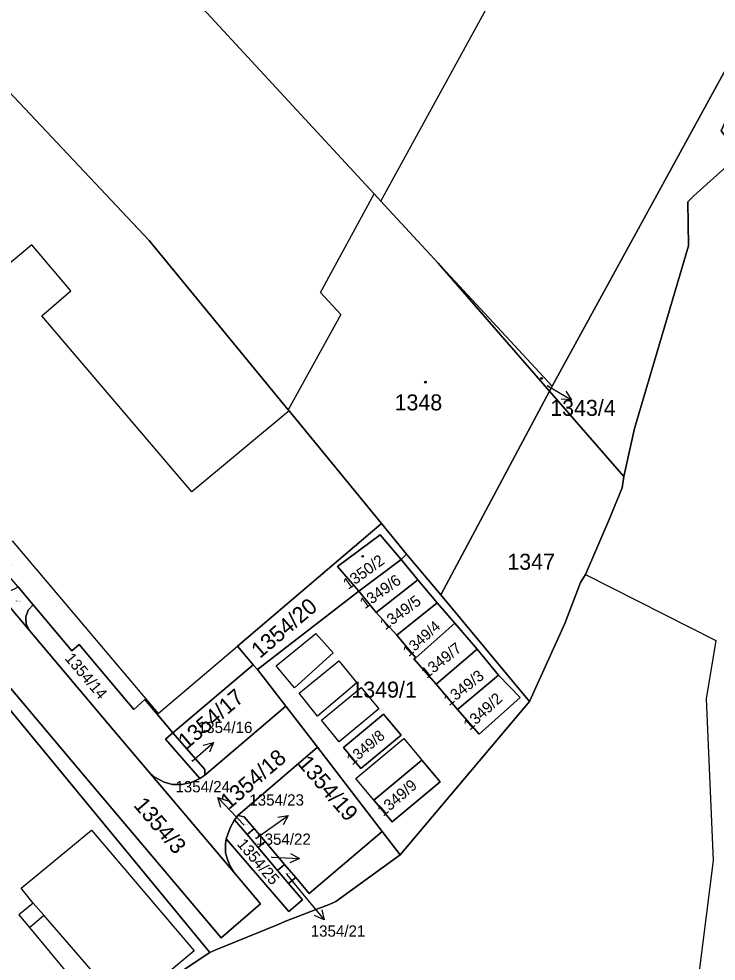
# Model space of a CAD drawing. Extents: x -598934 to -598196, y -1162208 to -1161502.
# Drawn here: x -598379.6 to -598305.5, y -1161704.6 to -1161604.5 of the extents above; entities that cross this region are included whole.
import ezdxf

# ---------------------------------------------------------------- set-up
doc = ezdxf.new("R2010")
doc.units = 0
for name, color, linetype in [('KN_CAR_KR', 7, 'Continuous'), ('KN_KULTURY', 7, 'Continuous'), ('KN_PARC_CIS_POM', 7, 'Continuous'), ('KN_PARC_CIS_POZ', 7, 'Continuous'), ('KN_PARC_CIS_STAV', 7, 'Continuous'), ('KN_PARC_PLOCHA', 7, 'Continuous'), ('PARC_C_SIPKA', 7, 'Continuous'), ('parcely_l', 7, 'Continuous')]:
    doc.layers.add(name, color=color, linetype=linetype)

msp = doc.modelspace()

# ---------------------------------------------------------------- linework, layer by layer
at = {"layer": 'KN_CAR_KR'}
for points in [[(-598341.18, -1161623.85), (-598303.83, -1161555.7)], [(-598347.6, -1161633.56), (-598341.89, -1161623.08)], [(-598378.28, -1161628.49), (-598381.33, -1161631.07)], [(-598374.13, -1161633.38), (-598378.28, -1161628.49)], [(-598377.19, -1161636.03), (-598374.13, -1161633.38)], [(-598345.44, -1161635.91), (-598347.6, -1161633.56)], [(-598361.28, -1161654.76), (-598377.19, -1161636.03)], [(-598345.44, -1161635.91), (-598351.03, -1161646.03)], [(-598350.93, -1161646.15), (-598361.28, -1161654.76)], [(-598380.37, -1161659.94), (-598364.85, -1161678.3)], [(-598319.42, -1161663.51), (-598305.58, -1161670.55)], [(-598352.29, -1161673.24), (-598348.1, -1161669.78)], [(-598348.1, -1161669.78), (-598346.23, -1161671.86)], [(-598305.58, -1161670.55), (-598306.62, -1161676.74)], [(-598364.85, -1161678.3), (-598356.42, -1161671.14)], [(-598346.23, -1161671.86), (-598350.37, -1161675.58)], [(-598349.85, -1161676.15), (-598345.63, -1161672.7)], [(-598345.63, -1161672.7), (-598343.74, -1161675.03)], [(-598350.37, -1161675.58), (-598352.29, -1161673.24)], [(-598343.74, -1161675.03), (-598347.9, -1161678.57)], [(-598347.48, -1161678.99), (-598343.26, -1161675.52)], [(-598343.26, -1161675.52), (-598341.38, -1161677.8)], [(-598347.9, -1161678.57), (-598349.85, -1161676.15)], [(-598306.62, -1161676.74), (-598305.85, -1161693.93)], [(-598341.38, -1161677.8), (-598345.61, -1161681.3)], [(-598345.61, -1161681.3), (-598347.48, -1161678.99)], [(-598343.83, -1161685.21), (-598338.73, -1161680.95)], [(-598338.73, -1161680.95), (-598336.81, -1161683.25)], [(-598341.91, -1161687.51), (-598343.83, -1161685.21)], [(-598379.41, -1161696.87), (-598371.93, -1161690.7)], [(-598371.93, -1161690.7), (-598361.01, -1161703.52)], [(-598305.85, -1161693.93), (-598308.81, -1161717.15)], [(-598378.13, -1161698.46), (-598379.41, -1161696.87)], [(-598378.13, -1161698.46), (-598379.64, -1161699.7)], [(-598376.98, -1161699.71), (-598378.13, -1161698.46)], [(-598379.64, -1161699.7), (-598378.53, -1161701.03)], [(-598378.53, -1161701.03), (-598376.98, -1161699.71)], [(-598368.4, -1161709.66), (-598376.98, -1161699.71)], [(-598378.53, -1161701.03), (-598370.21, -1161711.06)], [(-598361.01, -1161703.52), (-598368.4, -1161709.66)]]:
    msp.add_lwpolyline(points, dxfattribs=at)
at = {"layer": 'KN_KULTURY'}
for centre, radius in [((-598324.1, -1161642.69), 0.09), ((-598324.1, -1161642.69), 0.0398), ((-598336.44, -1161643.09), 0.09), ((-598336.44, -1161643.09), 0.0398), ((-598343.11, -1161661.59), 0.09), ((-598343.11, -1161661.59), 0.0398)]:
    msp.add_circle(centre, radius, dxfattribs=at)
at = {"layer": 'KN_PARC_PLOCHA'}
for points in [[(-598277.75, -1161561.08), (-598281.57, -1161567.88), (-598322.97, -1161643.5), (-598335.08, -1161630.46), (-598341.18, -1161623.85), (-598341.89, -1161623.08), (-598366.15, -1161596.79), (-598369.55, -1161593.36), (-598370.8, -1161592.1), (-598388.6, -1161574.13), (-598387.95, -1161573.46), (-598388.28, -1161573.14), (-598383.48, -1161567.99), (-598383.11, -1161568.33), (-598344.06, -1161526.26), (-598344.5, -1161525.85), (-598334.36, -1161514.94), (-598333.97, -1161515.3), (-598333.3, -1161514.67), (-598325, -1161522.8), (-598316.62, -1161529.5), (-598303.99, -1161539.63), (-598291.69, -1161549.87)], [(-598276.66, -1161561.96), (-598277.2, -1161562.77), (-598286.62, -1161581.38), (-598287.78, -1161580.83), (-598287.97, -1161581.19), (-598288.46, -1161581.06), (-598299.23, -1161601.96), (-598300.37, -1161603.49), (-598303.28, -1161612.54), (-598305.02, -1161616.39), (-598303.48, -1161618.34), (-598302.99, -1161619), (-598303.76, -1161619.55), (-598307.93, -1161623.3), (-598308.55, -1161623.92), (-598308.49, -1161628.62), (-598314.24, -1161648.01), (-598315.37, -1161653.13), (-598323.26, -1161644.05), (-598322.97, -1161643.5), (-598281.57, -1161567.88), (-598277.75, -1161561.08)], [(-598335.08, -1161630.46), (-598323.26, -1161644.05), (-598334.82, -1161665.7), (-598338.44, -1161661.36), (-598341.1, -1161658.12), (-598350.93, -1161646.15), (-598351.03, -1161646.03), (-598365.81, -1161628.03), (-598385.4, -1161607.3), (-598388.18, -1161604.36), (-598396.66, -1161595.57), (-598402.81, -1161589.15), (-598388.6, -1161574.13), (-598370.8, -1161592.1), (-598369.55, -1161593.36), (-598366.15, -1161596.79), (-598341.89, -1161623.08), (-598341.18, -1161623.85)], [(-598322.97, -1161643.5), (-598323.26, -1161644.05), (-598335.08, -1161630.46)], [(-598315.37, -1161653.13), (-598315.53, -1161654.3), (-598316.93, -1161657.69), (-598319.42, -1161663.51), (-598319.96, -1161664.37), (-598321.62, -1161668.74), (-598325.39, -1161677.01), (-598334.82, -1161665.7), (-598323.26, -1161644.05)], [(-598338.44, -1161661.36), (-598339.03, -1161661.94), (-598341.26, -1161659.3), (-598345.78, -1161662.67), (-598343.53, -1161665.3), (-598354.28, -1161673.63), (-598354.76, -1161673.11), (-598356.42, -1161671.14), (-598341.1, -1161658.12)], [(-598339.03, -1161661.94), (-598343.53, -1161665.3), (-598345.78, -1161662.67), (-598341.26, -1161659.3)], [(-598334.82, -1161665.7), (-598325.39, -1161677.01), (-598339.11, -1161693.31), (-598341.03, -1161690.82), (-598347.92, -1161681.88), (-598351.29, -1161677.51), (-598354.28, -1161673.63), (-598343.53, -1161665.3), (-598341.66, -1161667.57), (-598339.49, -1161669.96), (-598337.47, -1161672.38), (-598337.68, -1161672.47), (-598335.29, -1161675.17), (-598333.03, -1161677.87), (-598330.73, -1161680.49), (-598326.39, -1161676.59), (-598328.66, -1161674.24), (-598330.95, -1161671.46), (-598333.32, -1161668.71), (-598335.18, -1161666.53), (-598337.26, -1161664.08), (-598339.03, -1161661.94), (-598338.44, -1161661.36)], [(-598337.26, -1161664.08), (-598341.66, -1161667.57), (-598343.53, -1161665.3), (-598339.03, -1161661.94)], [(-598379.76, -1161664.8), (-598378.12, -1161666.75), (-598378.64, -1161667.32), (-598378.89, -1161668.03), (-598378.85, -1161668.8), (-598378.51, -1161669.49), (-598382.66, -1161664.58), (-598382.03, -1161665.02), (-598381.58, -1161665.23), (-598381.08, -1161665.32), (-598380.48, -1161665.24), (-598379.91, -1161664.94)], [(-598335.18, -1161666.53), (-598339.49, -1161669.96), (-598341.66, -1161667.57), (-598337.26, -1161664.08)], [(-598333.32, -1161668.71), (-598337.47, -1161672.38), (-598339.49, -1161669.96), (-598335.18, -1161666.53)], [(-598363.27, -1161680.35), (-598364.05, -1161681.02), (-598360.42, -1161685.21), (-598361.34, -1161685.63), (-598362.32, -1161685.84), (-598363.31, -1161685.83), (-598364.2, -1161685.6), (-598365.26, -1161685.02), (-598365.84, -1161684.5), (-598368.61, -1161681.22), (-598369.59, -1161680.06), (-598378.51, -1161669.49), (-598378.85, -1161668.8), (-598378.89, -1161668.03), (-598378.64, -1161667.32), (-598378.12, -1161666.75), (-598374, -1161671.63), (-598373.24, -1161670.97), (-598367.43, -1161677.86), (-598366.25, -1161676.82)], [(-598330.95, -1161671.46), (-598335.29, -1161675.17), (-598337.68, -1161672.47), (-598337.47, -1161672.38), (-598333.32, -1161668.71)], [(-598328.66, -1161674.24), (-598333.03, -1161677.87), (-598335.29, -1161675.17), (-598330.95, -1161671.46)], [(-598354.28, -1161673.63), (-598351.29, -1161677.51), (-598359.89, -1161684.85), (-598359.89, -1161684.24), (-598363.27, -1161680.35), (-598354.76, -1161673.11)], [(-598333.03, -1161677.87), (-598328.66, -1161674.24), (-598326.39, -1161676.59), (-598330.73, -1161680.49)], [(-598347.92, -1161681.88), (-598356.38, -1161689.13), (-598356.73, -1161689.58), (-598357.18, -1161690.45), (-598357.6, -1161691.63), (-598357.7, -1161692.13), (-598357.69, -1161693.1), (-598357.49, -1161693.82), (-598357.19, -1161694.52), (-598356.81, -1161695.16), (-598365.84, -1161684.5), (-598365.26, -1161685.02), (-598364.2, -1161685.6), (-598363.31, -1161685.83), (-598362.32, -1161685.84), (-598361.34, -1161685.63), (-598360.42, -1161685.21), (-598359.89, -1161684.85), (-598351.29, -1161677.51)], [(-598339.03, -1161680.6), (-598340.88, -1161678.36), (-598345.13, -1161681.92), (-598343.29, -1161684.14)], [(-598339.03, -1161680.6), (-598343.29, -1161684.14), (-598345.13, -1161681.92), (-598340.88, -1161678.36)], [(-598359.89, -1161684.85), (-598360.42, -1161685.21), (-598364.05, -1161681.02), (-598363.27, -1161680.35), (-598359.89, -1161684.24)], [(-598341.03, -1161690.82), (-598348.78, -1161697.43), (-598350.23, -1161695.71), (-598351.4, -1161694.34), (-598353.47, -1161691.9), (-598354.64, -1161690.53), (-598355.71, -1161689.28), (-598356.38, -1161689.13), (-598347.92, -1161681.88)], [(-598334.89, -1161685.56), (-598336.81, -1161683.25), (-598341.91, -1161687.51), (-598339.97, -1161689.8)], [(-598334.89, -1161685.56), (-598339.97, -1161689.8), (-598341.91, -1161687.51), (-598336.81, -1161683.25)], [(-598355.39, -1161691.17), (-598354.22, -1161692.54), (-598352.15, -1161694.98), (-598350.99, -1161696.35), (-598349.51, -1161698.11), (-598350.95, -1161699.34), (-598357.6, -1161691.63), (-598357.18, -1161690.45), (-598356.73, -1161689.58)], [(-598354.64, -1161690.53), (-598355.39, -1161691.17), (-598356.73, -1161689.58), (-598356.38, -1161689.13), (-598355.71, -1161689.28)], [(-598353.47, -1161691.9), (-598354.22, -1161692.54), (-598355.39, -1161691.17), (-598354.64, -1161690.53)], [(-598351.4, -1161694.34), (-598352.15, -1161694.98), (-598354.22, -1161692.54), (-598353.47, -1161691.9)], [(-598350.23, -1161695.71), (-598350.99, -1161696.35), (-598352.15, -1161694.98), (-598351.4, -1161694.34)]]:
    msp.add_lwpolyline(points, close=True, dxfattribs=at)
for points in [[(-598388.18, -1161604.36), (-598385.4, -1161607.3), (-598365.81, -1161628.03), (-598351.03, -1161646.03), (-598350.93, -1161646.15), (-598341.1, -1161658.12), (-598356.42, -1161671.14), (-598354.76, -1161673.11), (-598363.27, -1161680.35), (-598366.25, -1161676.82), (-598367.43, -1161677.86), (-598373.24, -1161670.97), (-598374, -1161671.63), (-598378.12, -1161666.75), (-598379.76, -1161664.8), (-598381.19, -1161663.11), (-598380.5, -1161662.52), (-598381.71, -1161661.08), (-598409.91, -1161627.67), (-598413.85, -1161622.48), (-598425.16, -1161610.26), (-598422.62, -1161607.5), (-598425.84, -1161604.52), (-598410.3, -1161587.66)], [(-598492.06, -1161676.4), (-598438.63, -1161618.4), (-598435.81, -1161615.34), (-598428.76, -1161622.69), (-598430.79, -1161624.72), (-598409.66, -1161643.2), (-598396.69, -1161658.7), (-598384.62, -1161673.23), (-598380.84, -1161677.59), (-598359.36, -1161703.7), (-598368.4, -1161709.66), (-598370.21, -1161711.06), (-598373.51, -1161714.16), (-598376.07, -1161708.98), (-598386.82, -1161714.43), (-598384.3, -1161719.62), (-598389.25, -1161722.01), (-598401.62, -1161728.95), (-598413, -1161741.14), (-598426.83, -1161755.55), (-598427.55, -1161756.32), (-598440.02, -1161777.77)], [(-598368.4, -1161709.66), (-598359.36, -1161703.7), (-598358.73, -1161703.42), (-598352.27, -1161700.8), (-598351.2, -1161700.32), (-598346.5, -1161698.53), (-598345.97, -1161698.27), (-598339.11, -1161693.31), (-598325.39, -1161677.01), (-598321.62, -1161668.74), (-598319.96, -1161664.37), (-598319.42, -1161663.51), (-598316.93, -1161657.69), (-598315.53, -1161654.3), (-598315.37, -1161653.13), (-598314.24, -1161648.01), (-598308.49, -1161628.62), (-598308.55, -1161623.92), (-598307.93, -1161623.3), (-598303.76, -1161619.55)], [(-598382.66, -1161664.58), (-598378.51, -1161669.49), (-598369.59, -1161680.06), (-598368.61, -1161681.22), (-598365.84, -1161684.5), (-598356.81, -1161695.16), (-598353.96, -1161698.52), (-598358.15, -1161702.12), (-598372.65, -1161684.98), (-598387.27, -1161667.65)], [(-598387.27, -1161667.65), (-598372.65, -1161684.98), (-598358.15, -1161702.12), (-598353.96, -1161698.52), (-598356.81, -1161695.16), (-598357.19, -1161694.52), (-598357.49, -1161693.82), (-598357.69, -1161693.1), (-598357.7, -1161692.13), (-598357.6, -1161691.63), (-598350.95, -1161699.34), (-598349.51, -1161698.11), (-598350.99, -1161696.35), (-598350.23, -1161695.71), (-598348.78, -1161697.43), (-598341.03, -1161690.82), (-598339.11, -1161693.31), (-598345.97, -1161698.27), (-598346.5, -1161698.53), (-598351.2, -1161700.32), (-598352.27, -1161700.8), (-598358.73, -1161703.42), (-598359.36, -1161703.7), (-598380.84, -1161677.59)]]:
    msp.add_lwpolyline(points, dxfattribs=at)
at = {"layer": 'PARC_C_SIPKA'}
for points in [[(-598323.49, -1161643.44), (-598320.91, -1161644.97)], [(-598321.51, -1161644.03), (-598320.91, -1161644.97), (-598322.02, -1161644.89)], [(-598361.23, -1161683.35), (-598358.97, -1161681.38)], [(-598360.05, -1161681.66), (-598358.97, -1161681.38), (-598359.39, -1161682.41)], [(-598358.17, -1161688.28), (-598358.49, -1161687.21), (-598357.44, -1161687.59)], [(-598355.7, -1161690.16), (-598356.43, -1161689.39), (-598358.49, -1161687.21)], [(-598354.47, -1161691.56), (-598353.48, -1161690.86), (-598351.02, -1161689.14)], [(-598352.13, -1161689.3), (-598351.02, -1161689.14), (-598351.55, -1161690.12)], [(-598352.81, -1161693.56), (-598349.81, -1161693.7)], [(-598350.79, -1161693.16), (-598349.81, -1161693.7), (-598350.84, -1161694.15)], [(-598351.19, -1161695.36), (-598349.1, -1161697.91), (-598347.2, -1161700.23)], [(-598347.45, -1161699.14), (-598347.2, -1161700.23), (-598348.22, -1161699.77)]]:
    msp.add_lwpolyline(points, dxfattribs=at)
at = {"layer": 'parcely_l'}
for points in [[(-598322.97, -1161643.5), (-598281.57, -1161567.88), (-598277.75, -1161561.08)], [(-598315.37, -1161653.13), (-598314.24, -1161648.01), (-598308.49, -1161628.62), (-598308.55, -1161623.92), (-598307.93, -1161623.3), (-598303.76, -1161619.55), (-598302.99, -1161619), (-598303.48, -1161618.34), (-598305.02, -1161616.39), (-598303.28, -1161612.54), (-598300.37, -1161603.49), (-598299.23, -1161601.96), (-598288.46, -1161581.06), (-598287.97, -1161581.19), (-598287.78, -1161580.83), (-598286.62, -1161581.38), (-598277.2, -1161562.77), (-598276.66, -1161561.96)], [(-598388.6, -1161574.13), (-598370.8, -1161592.1), (-598369.55, -1161593.36), (-598366.15, -1161596.79), (-598341.89, -1161623.08), (-598341.18, -1161623.85), (-598335.08, -1161630.46)], [(-598341.1, -1161658.12), (-598350.93, -1161646.15), (-598351.03, -1161646.03), (-598365.81, -1161628.03), (-598385.4, -1161607.3), (-598388.18, -1161604.36), (-598396.66, -1161595.57), (-598402.81, -1161589.15)], [(-598359.36, -1161703.7), (-598380.84, -1161677.59), (-598384.62, -1161673.23), (-598396.69, -1161658.7), (-598409.66, -1161643.2), (-598430.79, -1161624.72), (-598428.76, -1161622.69), (-598435.81, -1161615.34)], [(-598356.81, -1161695.16), (-598353.96, -1161698.52), (-598358.15, -1161702.12), (-598372.65, -1161684.98), (-598387.27, -1161667.65), (-598395.91, -1161657.42), (-598401.07, -1161651.3), (-598411.41, -1161639.04), (-598416.57, -1161632.87), (-598422.32, -1161625.96), (-598429.93, -1161616.73)], [(-598335.08, -1161630.46), (-598323.26, -1161644.05)], [(-598335.08, -1161630.46), (-598322.97, -1161643.5)], [(-598323.26, -1161644.05), (-598322.97, -1161643.5)], [(-598323.26, -1161644.05), (-598334.82, -1161665.7)], [(-598315.37, -1161653.13), (-598323.26, -1161644.05)], [(-598325.39, -1161677.01), (-598321.62, -1161668.74), (-598319.96, -1161664.37), (-598319.42, -1161663.51), (-598316.93, -1161657.69), (-598315.53, -1161654.3), (-598315.37, -1161653.13)], [(-598354.76, -1161673.11), (-598356.42, -1161671.14), (-598341.1, -1161658.12)], [(-598338.44, -1161661.36), (-598341.1, -1161658.12)], [(-598339.03, -1161661.94), (-598341.26, -1161659.3), (-598345.78, -1161662.67), (-598343.53, -1161665.3)], [(-598338.44, -1161661.36), (-598339.03, -1161661.94)], [(-598334.82, -1161665.7), (-598338.44, -1161661.36)], [(-598339.03, -1161661.94), (-598343.53, -1161665.3)], [(-598337.26, -1161664.08), (-598339.03, -1161661.94)], [(-598382.66, -1161664.58), (-598378.51, -1161669.49)], [(-598337.26, -1161664.08), (-598341.66, -1161667.57)], [(-598335.18, -1161666.53), (-598337.26, -1161664.08)], [(-598378.12, -1161666.75), (-598379.76, -1161664.8)], [(-598343.53, -1161665.3), (-598354.28, -1161673.63)], [(-598343.53, -1161665.3), (-598341.66, -1161667.57)], [(-598325.39, -1161677.01), (-598334.82, -1161665.7)], [(-598335.18, -1161666.53), (-598339.49, -1161669.96)], [(-598333.32, -1161668.71), (-598335.18, -1161666.53)], [(-598378.51, -1161669.49), (-598378.85, -1161668.8), (-598378.89, -1161668.03), (-598378.64, -1161667.32), (-598378.12, -1161666.75)], [(-598363.27, -1161680.35), (-598366.25, -1161676.82), (-598367.43, -1161677.86), (-598373.24, -1161670.97), (-598374, -1161671.63), (-598378.12, -1161666.75)], [(-598341.66, -1161667.57), (-598339.49, -1161669.96)], [(-598337.47, -1161672.38), (-598333.32, -1161668.71)], [(-598330.95, -1161671.46), (-598333.32, -1161668.71)], [(-598378.51, -1161669.49), (-598369.59, -1161680.06), (-598368.61, -1161681.22), (-598365.84, -1161684.5)], [(-598339.49, -1161669.96), (-598337.47, -1161672.38)], [(-598335.29, -1161675.17), (-598330.95, -1161671.46)], [(-598328.66, -1161674.24), (-598330.95, -1161671.46)], [(-598337.47, -1161672.38), (-598337.68, -1161672.47), (-598335.29, -1161675.17)], [(-598363.27, -1161680.35), (-598354.76, -1161673.11)], [(-598354.28, -1161673.63), (-598354.76, -1161673.11)], [(-598354.28, -1161673.63), (-598351.29, -1161677.51)], [(-598333.03, -1161677.87), (-598330.73, -1161680.49), (-598326.39, -1161676.59), (-598328.66, -1161674.24)], [(-598328.66, -1161674.24), (-598333.03, -1161677.87)], [(-598335.29, -1161675.17), (-598333.03, -1161677.87)], [(-598351.29, -1161677.51), (-598359.89, -1161684.85)], [(-598347.92, -1161681.88), (-598351.29, -1161677.51)], [(-598339.11, -1161693.31), (-598325.39, -1161677.01)], [(-598339.03, -1161680.6), (-598343.29, -1161684.14), (-598345.13, -1161681.92), (-598340.88, -1161678.36), (-598339.03, -1161680.6)], [(-598360.42, -1161685.21), (-598364.05, -1161681.02), (-598363.27, -1161680.35)], [(-598363.27, -1161680.35), (-598359.89, -1161684.24), (-598359.89, -1161684.85)], [(-598356.38, -1161689.13), (-598347.92, -1161681.88)], [(-598347.92, -1161681.88), (-598341.03, -1161690.82)], [(-598334.89, -1161685.56), (-598339.97, -1161689.8), (-598341.91, -1161687.51), (-598336.81, -1161683.25), (-598334.89, -1161685.56)], [(-598365.84, -1161684.5), (-598356.81, -1161695.16)], [(-598365.84, -1161684.5), (-598365.26, -1161685.02), (-598364.2, -1161685.6), (-598363.31, -1161685.83), (-598362.32, -1161685.84), (-598361.34, -1161685.63), (-598360.42, -1161685.21)], [(-598359.89, -1161684.85), (-598360.42, -1161685.21)], [(-598356.73, -1161689.58), (-598357.18, -1161690.45), (-598357.6, -1161691.63)], [(-598356.73, -1161689.58), (-598356.38, -1161689.13)], [(-598355.39, -1161691.17), (-598356.73, -1161689.58)], [(-598354.64, -1161690.53), (-598355.71, -1161689.28), (-598356.38, -1161689.13)], [(-598354.64, -1161690.53), (-598355.39, -1161691.17)], [(-598353.47, -1161691.9), (-598354.64, -1161690.53)], [(-598357.6, -1161691.63), (-598357.7, -1161692.13), (-598357.69, -1161693.1), (-598357.49, -1161693.82), (-598357.19, -1161694.52), (-598356.81, -1161695.16)], [(-598350.99, -1161696.35), (-598349.51, -1161698.11), (-598350.95, -1161699.34), (-598357.6, -1161691.63)], [(-598355.39, -1161691.17), (-598354.22, -1161692.54)], [(-598341.03, -1161690.82), (-598348.78, -1161697.43), (-598350.23, -1161695.71)], [(-598339.11, -1161693.31), (-598341.03, -1161690.82)], [(-598353.47, -1161691.9), (-598354.22, -1161692.54)], [(-598354.22, -1161692.54), (-598352.15, -1161694.98)], [(-598351.4, -1161694.34), (-598353.47, -1161691.9)], [(-598359.36, -1161703.7), (-598358.73, -1161703.42), (-598352.27, -1161700.8), (-598351.2, -1161700.32), (-598346.5, -1161698.53), (-598345.97, -1161698.27), (-598339.11, -1161693.31)], [(-598351.4, -1161694.34), (-598352.15, -1161694.98)], [(-598350.23, -1161695.71), (-598351.4, -1161694.34)], [(-598352.15, -1161694.98), (-598350.99, -1161696.35)], [(-598350.99, -1161696.35), (-598350.23, -1161695.71)], [(-598373.51, -1161714.16), (-598370.21, -1161711.06), (-598368.4, -1161709.66), (-598359.36, -1161703.7)]]:
    msp.add_lwpolyline(points, dxfattribs=at)

# ---------------------------------------------------------------- texts
at = {"layer": 'KN_PARC_CIS_POM'}
for s, p in [('1343/4', (-598323.6, -1161643.44)), ('1354/13', (-598379.99, -1161666.37)), ('1354/16', (-598361.39, -1161683.35)), ('1354/24', (-598355.86, -1161690.16)), ('1354/23', (-598354.63, -1161691.56)), ('1354/22', (-598352.97, -1161693.56)), ('1354/21', (-598351.35, -1161695.36))]:
    msp.add_text(s, height=0.1, dxfattribs=at).set_placement(p)
at = {"layer": 'KN_PARC_CIS_POZ'}
for s, height, p in [('1347', 1.7, (-598327.74, -1161663.02)), ('1349/1', 1.7, (-598344.31, -1161676.61)), ('1354/16', 1.2, (-598360.63, -1161680.37)), ('1354/24', 1.2, (-598363.01, -1161686.67)), ('1354/23', 1.2, (-598355.15, -1161688.08)), ('1354/22', 1.2, (-598354.42, -1161692.25)), ('1354/21', 1.2, (-598348.63, -1161702.01))]:
    msp.add_text(s, height=height, dxfattribs=at).set_placement(p)
for s, height, rotation, p in [('1349/6', 1.19, 35.6116, (-598342.88, -1161667.24)), ('1349/5', 1.19, 36.4019, (-598340.71, -1161669.48)), ('1354/20', 1.7, 40.5, (-598354.04, -1161672.52)), ('1349/4', 1.14, 42.0893, (-598338.21, -1161672.31)), ('1349/7', 1.19, 38.529, (-598336.29, -1161674.62)), ('1354/14', 1.2, 310.4983, (-598374.83, -1161672.48)), ('1349/3', 1.19, 38.4538, (-598333.92, -1161677.53)), ('1354/17', 1.7, 40.5, (-598361.82, -1161682.17)), ('1349/2', 1.19, 42.7956, (-598331.73, -1161680.16)), ('1349/8', 1.14, 40.1016, (-598344.22, -1161683.83)), ('1354/18', 1.7, 40.5, (-598357.34, -1161688.58)), ('1354/19', 1.7, 310.5, (-598350.1, -1161683.65)), ('1349/9', 1.19, 40.72, (-598340.92, -1161689.28)), ('1354/3', 1.7, 310.5006, (-598367.53, -1161688.09)), ('1354/25', 1.2, 310.4983, (-598356.53, -1161692.21))]:
    msp.add_text(s, height=height, rotation=rotation, dxfattribs=at).set_placement(p)
at = {"layer": 'KN_PARC_CIS_STAV'}
for s, p in [('1348', (-598339.72, -1161646.09)), ('1343/4', (-598323.18, -1161646.67))]:
    msp.add_text(s, height=1.7, dxfattribs=at).set_placement(p)
msp.add_text('1350/2', height=1.2, rotation=35.9998, dxfattribs=at).set_placement((-598344.65, -1161665.18))

doc.saveas('drawing.dxf')
